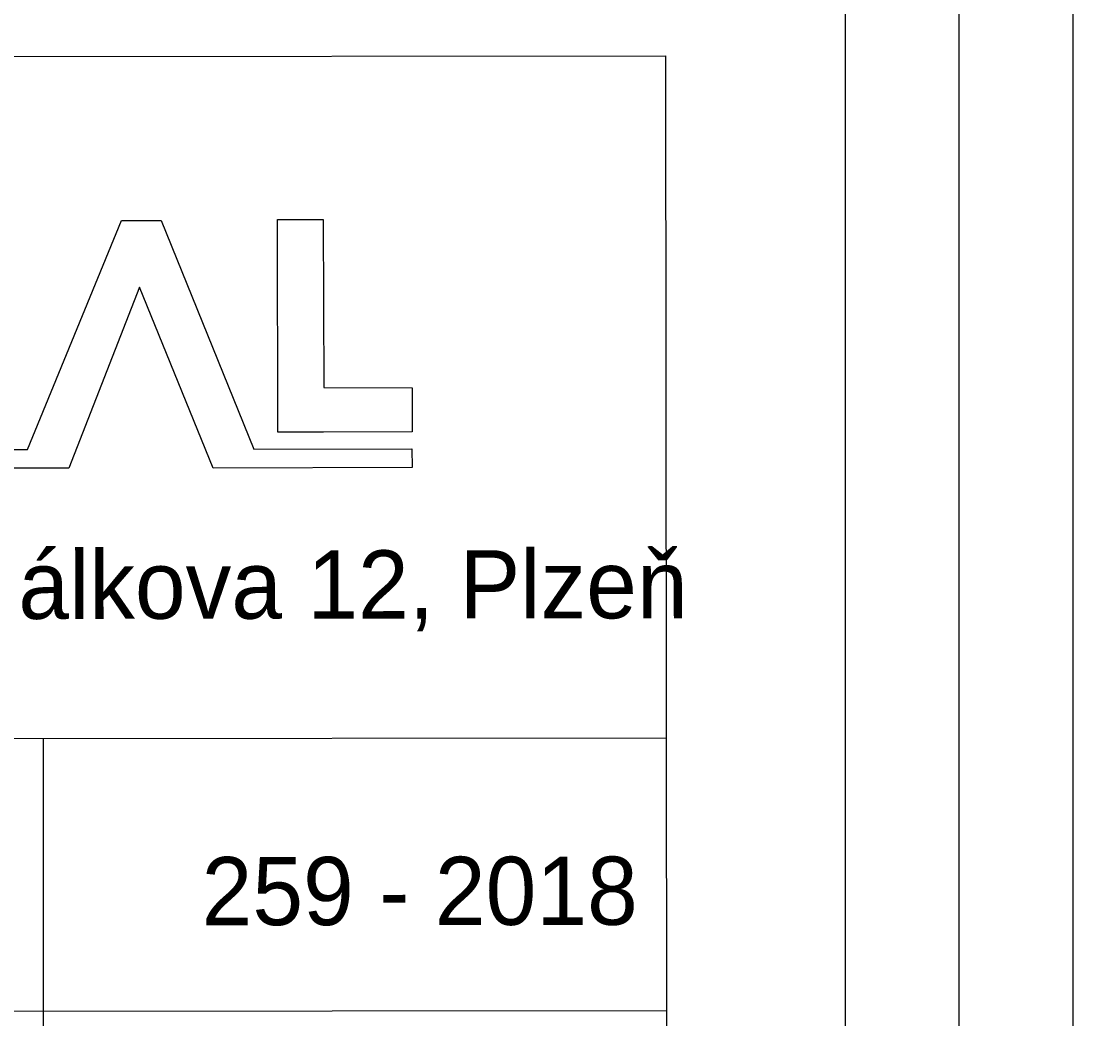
# Model space of a CAD drawing. Extents: x -761098.2 to -761034.2, y -1047998.6 to -1047967.9.
# Drawn here: x -761038.777 to -761034.151, y -1047993.481 to -1047989.091 of the extents above; entities that cross this region are included whole.
import ezdxf

# ---------------------------------------------------------------- set-up
doc = ezdxf.new("R2010")
doc.units = 0
for name, color, linetype in [('Default', 7, 'Continuous'), ('Rozpiska', 7, 'Continuous'), ('U_formát', 7, 'Continuous'), ('U_rozvržení_rámeček', 7, 'Continuous'), ('Z_Popisky', 7, 'Continuous')]:
    doc.layers.add(name, color=color, linetype=linetype)

# ---------------------------------------------------------------- blocks, each defined once
blk = doc.blocks.new('AnonymousCell-flat-1')
at = {"layer": 'Rozpiska'}
for p, q in [((24.562, 9.252), (26.548, 9.566)), ((24.562, 9.252), (26.548, 9.566)), ((26.548, 9.566), (27.72, 2.26)), ((26.548, 9.566), (27.72, 2.26)), ((26.024, 0.013), (24.562, 9.252)), ((26.024, 0.013), (24.562, 9.252)), ((17.802, 8.156), (19.514, 8.427)), ((17.802, 8.156), (19.514, 8.427)), ((19.514, 8.427), (25.091, -0.892)), ((19.514, 8.427), (25.091, -0.892)), ((15.259, -2.441), (17.802, 8.156)), ((15.259, -2.441), (17.802, 8.156)), ((19.029, 5.382), (17.188, -2.97)), ((19.029, 5.382), (17.188, -2.97)), ((23.455, -1.992), (19.029, 5.382)), ((23.455, -1.992), (19.029, 5.382)), ((27.72, 2.26), (31.566, 2.852)), ((27.72, 2.26), (31.566, 2.852)), ((31.566, 2.852), (31.865, 0.935)), ((31.566, 2.852), (31.865, 0.935)), ((31.865, 0.935), (28.01, 0.327)), ((31.865, 0.935), (28.01, 0.327)), ((25.091, -0.892), (31.958, 0.195)), ((25.091, -0.892), (31.958, 0.195)), ((28.01, 0.327), (26.024, 0.013)), ((28.01, 0.327), (26.024, 0.013)), ((31.958, 0.195), (32.108, -0.616)), ((31.958, 0.195), (32.108, -0.616)), ((32.108, -0.616), (23.455, -1.992)), ((32.108, -0.616), (23.455, -1.992)), ((-30.481, -9.671), (15.259, -2.441)), ((-30.481, -9.671), (15.259, -2.441)), ((17.188, -2.97), (-30.357, -10.494)), ((17.188, -2.97), (-30.357, -10.494))]:
    blk.add_line(p, q, dxfattribs=at)
for points in [[(24.562, 9.252), (26.548, 9.566), (27.72, 2.26), (31.566, 2.852), (31.865, 0.935), (28.01, 0.327), (26.024, 0.013), (24.562, 9.252)], [(24.562, 9.252), (26.548, 9.566), (27.72, 2.26), (31.566, 2.852), (31.865, 0.935), (28.01, 0.327), (26.024, 0.013), (24.562, 9.252)], [(17.802, 8.156), (19.514, 8.427), (25.091, -0.892), (31.958, 0.195), (32.108, -0.616), (23.455, -1.992), (19.029, 5.382), (17.188, -2.97), (-30.357, -10.494), (-30.481, -9.671), (15.259, -2.441), (17.802, 8.156)], [(17.802, 8.156), (19.514, 8.427), (25.091, -0.892), (31.958, 0.195), (32.108, -0.616), (23.455, -1.992), (19.029, 5.382), (17.188, -2.97), (-30.357, -10.494), (-30.481, -9.671), (15.259, -2.441), (17.802, 8.156)]]:
    blk.add_lwpolyline(points, dxfattribs=at)
blk = doc.blocks.new('U1096')
at = {"layer": 'Default'}
blk.add_lwpolyline([(0, -297), (0, 0), (-630, 0), (-630, -297)], close=True, dxfattribs=at)
at = {"layer": 'U_formát'}
for points in [[(-635, 5), (5, 5), (5, -302), (-635, -302)], [(-5, -292), (-5, -5), (-625, -5), (-625, -292)]]:
    blk.add_lwpolyline(points, close=True, dxfattribs=at)

msp = doc.modelspace()

# ---------------------------------------------------------------- linework, layer by layer
at = {"layer": 'Rozpiska'}
for p, q in [((-761053.2955, -1047989.2605), (-761035.9406, -1047989.2441)), ((-761053.2406, -1047989.2604), (-761035.9406, -1047989.2441)), ((-761035.9332, -1047997.0441), (-761035.9406, -1047989.2441)), ((-761035.9332, -1047997.0441), (-761035.9406, -1047989.2441)), ((-761053.2927, -1047992.2605), (-761035.9378, -1047992.2441)), ((-761053.2378, -1047992.2604), (-761035.9378, -1047992.2441)), ((-761038.6806, -1047992.2467), (-761038.6775, -1047997.0467)), ((-761038.6806, -1047992.2467), (-761038.6775, -1047997.0467)), ((-761040.7876, -1047993.4486), (-761035.9367, -1047993.4441)), ((-761040.7876, -1047993.4486), (-761035.9367, -1047993.4441))]:
    msp.add_line(p, q, dxfattribs=at)

# ---------------------------------------------------------------- block references
at = {"layer": 'U_rozvržení_rámeček', "xscale": 0.1, "yscale": 0.10000000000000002}
msp.add_blockref('U1096', (-761034.6506, -1047968.4285), dxfattribs=at)
at = {"layer": 'Z_Popisky', "xscale": 0.09999999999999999, "yscale": 0.10000000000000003, "rotation": -8.873281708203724}
msp.add_blockref('AnonymousCell-flat-1', (-761040.2194, -1047990.4993), dxfattribs=at)

# ---------------------------------------------------------------- texts
at = {"layer": 'Rozpiska'}
for s, p in [('GEOREAL spol. s r.o., Hálkova 12, Plzeň', (-761043.2033, -1047991.7253)), ('259 - 2018', (-761037.9828, -1047993.0688))]:
    msp.add_text(s, height=0.3, rotation=0.0542, dxfattribs=at).set_placement(p)

doc.saveas('drawing.dxf')
